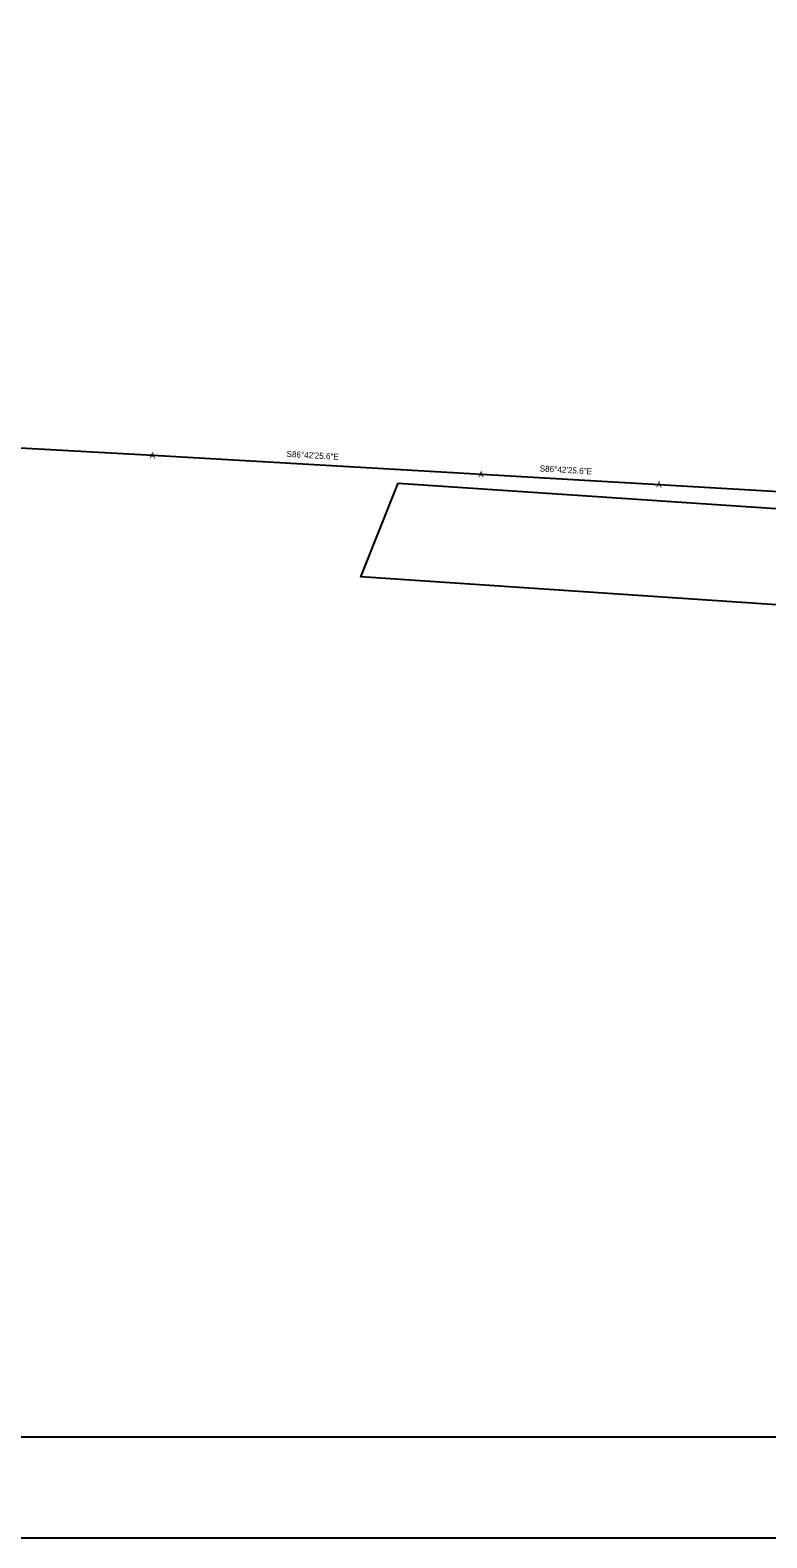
# Model space of a CAD drawing. Extents: x 679444 to 687671, y 733868 to 736107.
# Drawn here: x 684641 to 685370, y 733868 to 735359 of the extents above; entities that cross this region are included whole.
import ezdxf

# ---------------------------------------------------------------- set-up
doc = ezdxf.new("R2010")
doc.units = 0
for name, color, linetype in [('$', 7, 'Continuous'), ('C-TOPO', 7, 'Continuous'), ('C-TOPO-FEAT', 7, 'Continuous'), ('Clipping Boundary', 7, 'Continuous'), ('R_Horz Alg', 7, 'Continuous'), ('R_Horz Alg Station', 7, 'Continuous'), ('V-NODE', 7, 'Continuous')]:
    doc.layers.add(name, color=color, linetype=linetype)

msp = doc.modelspace()

# ---------------------------------------------------------------- linework, layer by layer
at = {"layer": '$'}
msp.add_lwpolyline([(679553.9, 733968.3), (687571.1, 733968.3), (687571.1, 736006.7), (679553.9, 736006.7), (679553.9, 733968.3)], dxfattribs=at)
at = {"layer": 'C-TOPO'}
msp.add_lwpolyline([(679453.9, 733868.3), (687671.1, 733868.3), (687671.1, 736106.7), (679453.9, 736106.7), (679453.9, 733868.3)], dxfattribs=at)
at = {"layer": 'C-TOPO-FEAT'}
msp.add_lwpolyline([(679553.9, 733968.3), (687571.1, 733968.3), (687571.1, 736006.7), (679553.9, 736006.7), (679553.9, 733968.3)], dxfattribs=at)
at = {"layer": 'Clipping Boundary'}
msp.add_lwpolyline([(685005, 734911.3), (685870.8, 734853.2), (685958.9, 734834.2), (686124.4, 734817.1), (686182.4, 734811.1), (686223.6, 734766), (686227.9, 734744.6), (686187.4, 734736.6), (684968, 734818.5)], close=True, dxfattribs=at)
at = {"layer": 'R_Horz Alg Station'}
for p, q in [((683955.1, 734983.8), (684762.2, 734938.7)), ((684762.2, 734938.7), (685087.3, 734919.9)), ((685087.3, 734919.9), (685263.4, 734909.8)), ((685263.4, 734909.8), (685617.9, 734889.4))]:
    msp.add_line(p, q, dxfattribs=at)
at = {"layer": 'V-NODE'}
msp.add_lwpolyline([(679553.9, 733968.3), (687571.1, 733968.3), (687571.1, 736006.7), (679553.9, 736006.7), (679553.9, 733968.3)], dxfattribs=at)

# ---------------------------------------------------------------- texts
at = {"layer": 'R_Horz Alg'}
for rotation, p in [(356.753, (684759, 734935.8)), (356.7071, (685084.2, 734917.1)), (356.7071, (685260.3, 734907))]:
    msp.add_text('A', height=6, rotation=rotation, dxfattribs=at).set_placement(p)
at = {"layer": 'R_Horz Alg Station'}
for p in [(684894.3, 734937.2), (685144.9, 734922.8)]:
    msp.add_text('S86%%d42\'25.6"E', height=6, rotation=356.7071, dxfattribs=at).set_placement(p)

doc.saveas('drawing.dxf')
